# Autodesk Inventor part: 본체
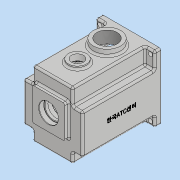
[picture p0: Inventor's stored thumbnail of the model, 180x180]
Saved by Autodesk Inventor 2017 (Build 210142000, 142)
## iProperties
Part Number: 본체
Material: 일반
Document SubType Name: Modeling
Designer: MRC
Density: 1 g/cm^3
Appearance: 기본값
Mass: 520.092 g
Surface Area: 1170.72 cm^2
Volume: 520.092 cm^3
Author: MRC
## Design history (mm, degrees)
sketch "스케치1"
  geometry: L1 (-49, 55)-(49, 55); L2 (49, 55)-(49, -55); L3 (49, -55)-(-49, -55); L4 (-49, -55)-(-49, 55); L5 (-49, 55)-(49, -55); L6 (49, 55)-(-49, -55); 1 further point
  constraints: 12 end point, 2 midpoint, 2 parallel, 1 horizontal, 1 perpendicular
  dimensions: "d0" = 98 distance of L2.end L3.end; "d1" = 110 distance of L1.end L2.end
extrude "돌출1" new body sketch "스케치1" stored distance "d2" = 130; taper "d3" = 0 deg
sketch "스케치4"
  geometry: L1 (0, 0)-(16, 0); L2 (16, 0)-(16, 120); L3 (16, 120)-(0, 120); L4 (0, 120)-(0, 0); L5 (0, 0)-(16, 120); L6 (16, 0)-(0, 120); L7 (98, 0)-(0, 0) reference; L8 (82, 0)-(98, 0); L9 (98, 0)-(98, 120); L10 (98, 120)-(82, 120); L11 (82, 120)-(82, 0); L12 (82, 0)-(98, 120); L13 (98, 0)-(82, 120); 3 further points
  constraints: 24 end point, 4 midpoint, 4 parallel, 2 collinear, 2 horizontal, 2 perpendicular
  dimensions: "d12" = 16 distance of L3.end L2.end; "d13" = 120 distance of L2.end L1.end; "d14" = 16 distance of L10.end L9.end; "d15" = 120 distance of L7.start L9.end
extrude "돌출4" cut sketch "스케치4" distance "d16" = 27; taper "d17" = 0 deg
sketch "스케치5"
  geometry: L1 (98, 0)-(82, 0); L2 (82, 0)-(82, -120); L3 (82, -120)-(98, -120); L4 (98, -120)-(98, 0); L5 (98, 0)-(82, -120); L6 (82, 0)-(98, -120); L7 (0, 0)-(98, 0) reference; L8 (16, 0)-(0, 0); L9 (0, 0)-(0, -120); L10 (0, -120)-(16, -120); L11 (16, -120)-(16, 0); L12 (16, 0)-(0, -120); L13 (0, 0)-(16, -120); 3 further points
  constraints: 24 end point, 4 midpoint, 4 parallel, 2 collinear, 2 horizontal, 2 perpendicular
  dimensions: "d18" = 16 distance of L3.end L2.end; "d19" = 120 distance of L2.end L1.end; "d20" = 16 distance of L10.end L9.end; "d21" = 120 distance of L7.start L9.end
extrude "돌출5" cut sketch "스케치5" distance "d22" = 17; taper "d23" = 0 deg
sketch "스케치9"
  geometry: L1 (49, 55)-(-49, 55) reference; L2 (-49, 55)-(-49, -55) reference; C1 r 3.5 at (-42, 48); 1 further point
  constraints: 1 centre point
  dimensions: "d31" = 7 diameter of C1; "d32" = 7 distance from line of C1.centre L1; "d33" = 7 distance from line of L2 C1.centre
extrude "돌출8" cut sketch "스케치9" stored distance "d34" = 8.3; taper "d35" = 0 deg
sketch "스케치2"
  geometry: L1 (0, 130)-(98, 130) reference; C1 r 22.5 at (49, 90); 1 further point
  constraints: 1 centre point, 1 vertical alignment
  dimensions: "d4" = 45 diameter of C1; "d5" = 40 distance from line of C1.centre L1
extrude "돌출2" join sketch "스케치2" distance "d6" = 10; taper "d7" = 0 deg
sketch "스케치3"
  geometry: C1 r 15 at (49, 41); C2 r 22.5 at (49, 90) reference; 1 further point
  constraints: 1 centre point, 1 vertical alignment
  dimensions: "d8" = 30 diameter of C1; "d9" = 49 distance of C1.centre C2.centre
extrude "돌출3" join sketch "스케치3" distance "d10" = 5; taper "d11" = 0 deg
sketch "스케치10"
  geometry: L1 (-49, -55)-(49, -55) reference; L2 (-23, 45)-(23, 45); L3 (-23, 45)-(-23, 30.143); L4 (23, 45)-(23, 30.143); A1 r 42 centre (0, -5) between (-23, 30.143) and (23, 30.143); 2 further points
  constraints: 6 end point, 2 point on circle, 2 vertical, 2 vertical alignment, 1 centre point, 1 horizontal, 1 midpoint
  dimensions: "d42" = 84 diameter of A1; "d43" = 50 distance from line of L1 A1.centre; "d45" = 50 distance from line of A1.centre L2; "d46" = 46 distance of L2.start L2.end
extrude "돌출9" cut sketch "스케치10" distance "d47" = 121; taper "d48" = 0 deg
fillet "모깎기1" dims "d49" = 6
fillet "모깎기2" dims "d50" = 3
sketch "스케치11"
  geometry: L1 (-20, 45)-(20, 45) reference; L2 (-23, 33.249)-(-23, 42) reference; L3 (23, 42)-(23, 33.249) reference; L4 (-26, 33.249)-(-26, 42); L5 (-20, 48)-(20, 48); L6 (26, 42)-(26, 33.249); A1 r 3 centre (20, 42) between (23, 42) and (20, 45) reference; A2 r 3 centre (-20, 42) between (-20, 45) and (-23, 42) reference; A3 r 6 centre (-29, 33.249) between (-25.375, 28.468) and (-23, 33.249) reference; A4 r 42 centre (0, -5) between (-25.375, 28.468) and (25.375, 28.468) reference; A5 r 6 centre (29, 33.249) between (23, 33.249) and (25.375, 28.468) reference; A6 r 45 centre (0, -5) between (-27.187, 30.859) and (27.188, 30.859); A7 r 3 centre (-29, 33.249) between (-27.187, 30.859) and (-26, 33.249); A8 r 6 centre (-20, 42) between (-20, 48) and (-26, 42); A9 r 6 centre (20, 42) between (26, 42) and (20, 48); A10 r 3 centre (29, 33.249) between (26, 33.249) and (27.188, 30.859); 1 further point
  constraints: 10 point on circle, 6 end point, 5 centre point, 7 other
  dimensions: "d51" = 3 radial gap between concentric circles of A4 A6
extrude "돌출10" cut sketch "스케치11" distance "d52" = 9; taper "d53" = 0 deg
hole "구멍1" diameter "d56" = 33.376; stored, may be unused: countersink angle "d60" = 90 deg, drill point angle "d62" = 118 deg; dims "d54" = 10, "d55" = 10, "d57" = 70, "d58" = 4, "d59" = 2, "d61" = 77.3
sketch "스케치12"
  geometry: C1 r 15 at (20, -32) reference; 1 further point
extrude "돌출11" cut sketch "스케치12" distance "d63" = 5; taper "d64" = 0 deg
sketch "스케치13"
  geometry: C1 r 10 at (0, 0); C2 r 15 at (0, 0) reference; 1 further point
  constraints: 1 centre point, 1 concentric
  dimensions: "d65" = 20 diameter of C1
extrude "돌출12" cut sketch "스케치13" stored distance "d66" = 5; taper "d67" = 0 deg
sketch "스케치14"
  geometry: A1 r 21 centre (0, 6) between (8.978, -12.984) and (-8.978, -12.984); A2 r 42 centre (0, -5) between (-25.375, 28.468) and (25.375, 28.468) reference; A3 r 15 centre (0, -25) between (-8.978, -12.984) and (8.978, -12.984); 1 further point
  constraints: 4 point on circle, 2 centre point, 2 vertical alignment
  dimensions: "d68" = 42 diameter of A1; "d69" = 11 distance of A1.centre A2.centre; "d70" = 30 diameter of A3; "d71" = 20 distance of A3.centre A2.centre
extrude "돌출13" join sketch "스케치14" distance "d72" = 7; taper "d73" = 0 deg
sketch "스케치15"
  geometry: C1 r 17.5 at (0, 6); A1 r 21 centre (0, 6) between (8.978, -12.984) and (-8.978, -12.984) reference; 1 further point
  constraints: 1 centre point, 1 concentric
  dimensions: "d74" = 35 diameter of C1
extrude "돌출14" cut sketch "스케치15" distance "d75" = 10; taper "d76" = 0 deg
sketch "스케치16"
  geometry: C1 r 14 at (0, 0); C2 r 17.5 at (0, 0) reference; 1 further point
  constraints: 1 centre point, 1 concentric
  dimensions: "d77" = 28 diameter of C1
extrude "돌출15" cut sketch "스케치16" stored distance "d78" = 10; taper "d79" = 0 deg
sketch "스케치17"
  geometry: L1 (-27, 33)-(27, 33); L2 (27, 33)-(27, -21); L3 (27, -21)-(-27, -21); L4 (-27, -21)-(-27, 33); L5 (-27, 33)-(27, -21); L6 (27, 33)-(-27, -21); C1 r 14 at (0, 6) reference; 1 further point
  constraints: 12 end point, 2 midpoint, 2 parallel, 1 horizontal, 1 perpendicular
  dimensions: "d80" = 54 distance of L2.end L3.end; "d81" = 54 distance of L1.end L2.end
extrude "돌출16" join sketch "스케치17" distance "d82" = 7; taper "d83" = 0 deg
sketch "스케치18"
  geometry: C1 r 14 at (0, 6) reference; C2 r 16 at (0, 6); 1 further point
  constraints: 1 centre point, 1 coincident
  dimensions: "d84" = 32 diameter of C2
extrude "돌출17" cut sketch "스케치18" distance "d85" = 8.3; taper "d86" = 0 deg
sketch "스케치19"
  geometry: C1 r 11 at (0, -25); A1 r 15 centre (0, -25) between (-8.978, -12.984) and (8.978, -12.984) reference; 1 further point
  constraints: 1 centre point, 1 concentric
  dimensions: "d87" = 22 diameter of C1
extrude "돌출18" cut sketch "스케치19" distance "d88" = 7; taper "d89" = 0 deg
sketch "스케치20"
  geometry: C1 r 9.5 at (0, 0); C2 r 11 at (0, 0) reference; 1 further point
  constraints: 1 centre point, 1 concentric
  dimensions: "d90" = 19 diameter of C1
extrude "돌출19" cut sketch "스케치20" distance "d91" = 3; taper "d92" = 0 deg
sketch "스케치21"
  geometry: L1 (-41.809, -9)-(-35.777, -9); L2 (-41.809, -1)-(-35.777, -1); L3 (35.777, -9)-(41.809, -9); L4 (35.777, -1)-(41.809, -1); A1 r 36 centre (0, -5) between (36, -5) and (-36, -5); A2 r 42 centre (0, -5) between (-25.375, 28.468) and (25.375, 28.468) reference; A3 r 4 centre (-36, -5) between (-36, -9) and (-36, -1); A4 r 4 centre (36, -5) between (36, -1) and (36, -9); 1 further point
  constraints: 14 point on circle, 8 end point, 4 horizontal, 4 point on line, 4 tangent, 3 centre point, 2 horizontal alignment, 1 concentric, 1 equal radius
  dimensions: "d93" = 72 diameter of A1; "d94" = 8 diameter of A3
extrude "돌출20" join sketch "스케치21" stored distance "d95" = 3; taper "d96" = 0 deg
fillet "모깎기3" dims "d97" = 3
fillet "모깎기4" dims "d98" = 3
fillet "모깎기5" dims "d99" = 3
fillet "모깎기6" dims "d100" = 3
sketch "스케치22"
  geometry: A1 r 4 centre (-36, -5) between (-36, -9) and (-36, -1) reference; 2 further points
  constraints: 1 coincident
hole "구멍2" sketch "스케치22" at (-36, -5) diameter "d101" = 3.242; stored, may be unused: countersink angle "d105" = 90 deg, drill point angle "d107" = 118 deg; dims "d102" = 7, "d103" = 4, "d104" = 2, "d106" = 9
fillet "모깎기7" dims "d108" = 3
fillet "모깎기8" dims "d109" = 3
fillet "모깎기9" dims "d110" = 3
fillet "모깎기10" dims "d111" = 3
chamfer "모따기1" distance "d112" = 1; stored, may be unused: second distance "d113" = 2, angle "d114" = 45 deg
chamfer "모따기2" distance "d115" = 0.8; stored, may be unused: second distance "d116" = 2, angle "d117" = 30 deg
sketch "스케치23"
  geometry: L1 (-130, 104)-(-130, 83) reference; L2 (-13, 80)-(-127, 80) reference; 2 further points
  constraints: 1 other
  dimensions: "d118" = 65 distance from line of L1 point (-65, 47); "d119" = 33 distance from line of point (-65, 47) L2
feature "엠보싱1" sketch "스케치23" dims "d120" = 0.5, "d121" = 0
fillet "모깎기11" dims "d122" = 0.3
fillet "모깎기12" dims "d123" = 3
node "솔리드1"
pattern_linear "직사각형 패턴1" dims "d38" = 96, "d41" = 84
mirror "미러1"
node "투영된 루프1"
